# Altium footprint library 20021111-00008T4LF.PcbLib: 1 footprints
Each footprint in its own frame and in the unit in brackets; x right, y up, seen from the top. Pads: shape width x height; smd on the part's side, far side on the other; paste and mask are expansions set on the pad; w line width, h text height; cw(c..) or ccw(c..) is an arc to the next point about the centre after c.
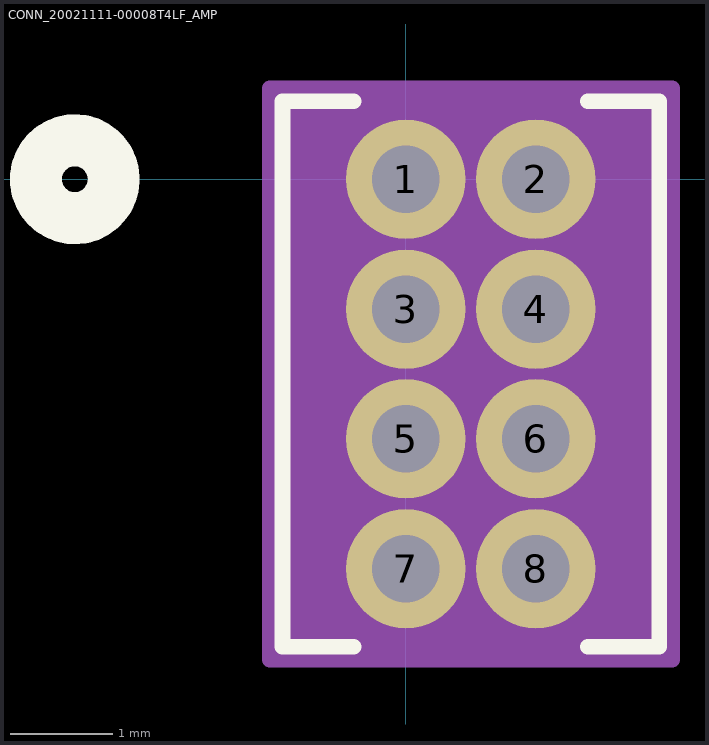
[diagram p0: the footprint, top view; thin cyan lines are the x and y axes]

## CONN_20021111-00008T4LF_AMP [mil]
pads (8):
  round 46 hole 26 paste-23 mask+0: 1(0,0) 2(50,0) 3(0,-50) 4(50,-50) 5(0,-100) 6(50,-100) 7(0,-150) 8(50,-150)
Top Overlay:
  circle w20: c-127.52,0 r15
  lines w6: -20.08,-180 -47.52,-180 -47.52,30 -20.08,30 ; 70.08,-180 97.52,-180 97.52,30 70.08,30
  text ".Designator" at -112.5,-100 h50
Bottom Overlay:
  circle w20: c-127.52,0 r15
Mechanical 13:
  circle w20: c0,0 r15
  lines w1: -42.52,-175 92.52,-175 92.52,25 -42.52,25 -42.52,-175
  text ".Designator" at -112.5,-100 h50
Mechanical 15:
  region: 102.52,35 -52.52,35 -52.52,-185 102.52,-185
  lines w6: -52.52,-185 -52.52,35 102.52,35 102.52,-185 -52.52,-185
